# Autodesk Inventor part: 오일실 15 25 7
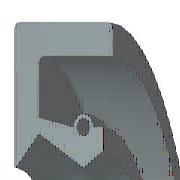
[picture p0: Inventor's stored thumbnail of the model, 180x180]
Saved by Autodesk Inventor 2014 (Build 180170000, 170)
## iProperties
Created: 2012-02
Part Number: 오일실 15 25 7
Material: 고무
Description: 오일-실
Document SubType Name: Modeling
Standard: KS B 2804
Designer: mduedu
Standards Organization: KS
Language: ko-KR
Size Designation: D - 15 25 7
Categories: <MemberInstance><Categories><Category DisplayName="샤프트 부품" InternalName="7f7aeb1f-a693-4053-b835-cee3144e0d98" Mnemonic="SHFT"><Category DisplayName="실링" Intern
Density: 0.93 g/cm^3
Appearance: 고무 - 검은색 - 버전 1.1
IsCustomPart: 1
Author: mduedu
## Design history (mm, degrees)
revolve "본체" stored, may be unused: angle "d17" = 90 deg
revolve "스프링1" stored, may be unused: angle "d18" = 90 deg
body "Solid1"
sketch "스케치1"
  geometry: L1 (0, 12.5)-(7, 12.5); L2 (7, 10.75)-(1.75, 10.75); L3 (1.75, 9.25)-(4.9, 7.5); L4 (4.9, 7.5)-(0, 7.5); L5 (0, 0)-(9.586, 0) reference; L6 (4.9, 7.5)-(6.3, 8.375); L7 (0, 18)-(0, -3) reference; L8 (-1.941, 0)-(11.507, 0) reference; L9 (4.2, 9.6)-(1.75, 10.09); L10 (1.75, 10.09)-(1.75, 10.75); L11 (0, 12.5)-(0, 7.588); L12 (4.9, 7.5)-(0, 7.5); L13 (1.75, 9.25)-(0.152, 7.528); L14 (7, 12.5)-(7, 10.75); L15 (5.6, 9.6)-(6.3, 9.6); L16 (6.3, 9.6)-(6.3, 8.375); C1 r 0.455 at (4.9, 9.6); A1 r 0.7 centre (4.9, 9.6) between (5.6, 9.6) and (4.2, 9.6); A2 r 0.088 centre (0.088, 7.588) between (0, 7.588) and (0.152, 7.528); 1 further point
  constraints: 28 end point, 5 horizontal alignment, 5 point on line, 4 point on circle, 4 vertical alignment, 3 centre point, 3 tangent, 2 collinear, 2 horizontal, 2 perpendicular, 1 coincident, 1 parallel
  dimensions: "d0" = 25 diameter of L1 L5 (= SD2); "d1" = 1.75 distance of L1.end L2.start (= SD); "d2" = 0.91 diameter of C1 (= SPDI); "d3" = 1.4 diameter of A1 (= SPDA); "d4" = 15 diameter of L3.end L5 (= NND); "d5" = 18.5 diameter of L3.start L5 (= TKDM); "d7" = 20.18 diameter of L9.end L5 (= TKDM + 0.24 x SWDT); "d8" = 1.75 distance between parallel lines of L11 L10 (= SD); "d9" = 4.9 distance from line of L11 C1.centre (= SPDST); "d10" = 19.2 diameter of C1.centre L5 (= HLDM); "d11" = 0.0875 radius of A2 (= 0.25 x LAB); "d12" = 6.3 distance between parallel lines of L11 L16 (= SDI); "d13" = 16.75 diameter of L6.end L5 (= ABDM); "d14" = 7 distance from line of L11 L1.end (= SWDT)
fillet "모깎기1" dims "d6" = 0.3 (= RR)
other parameters: "SD2" = 25 [user parameter; used in 1 equation term], "SWDT" = 7 [user parameter; used in 2 equation terms], "RR" = 0.3 [user parameter; used in 1 equation term], "SD" = 1.75 [user parameter; used in 2 equation terms], "NND" = 15 [user parameter; used in 1 equation term], "SPDA" = 1.4 [user parameter; used in 1 equation term], "SPDI" = 0.91 [user parameter; used in 1 equation term], "TKDM" = 18.5 [user parameter; used in 2 equation terms], "HLDM" = 19.2 [user parameter; used in 1 equation term], "ABDM" = 16.75 [user parameter; used in 1 equation term], "SDI" = 6.3 [user parameter; used in 1 equation term], "SPDST" = 4.9 [user parameter; used in 1 equation term], "LAB" = 0.35 [user parameter; used in 1 equation term], "d15" = 0, "d16" = 0, "d19" = 0
